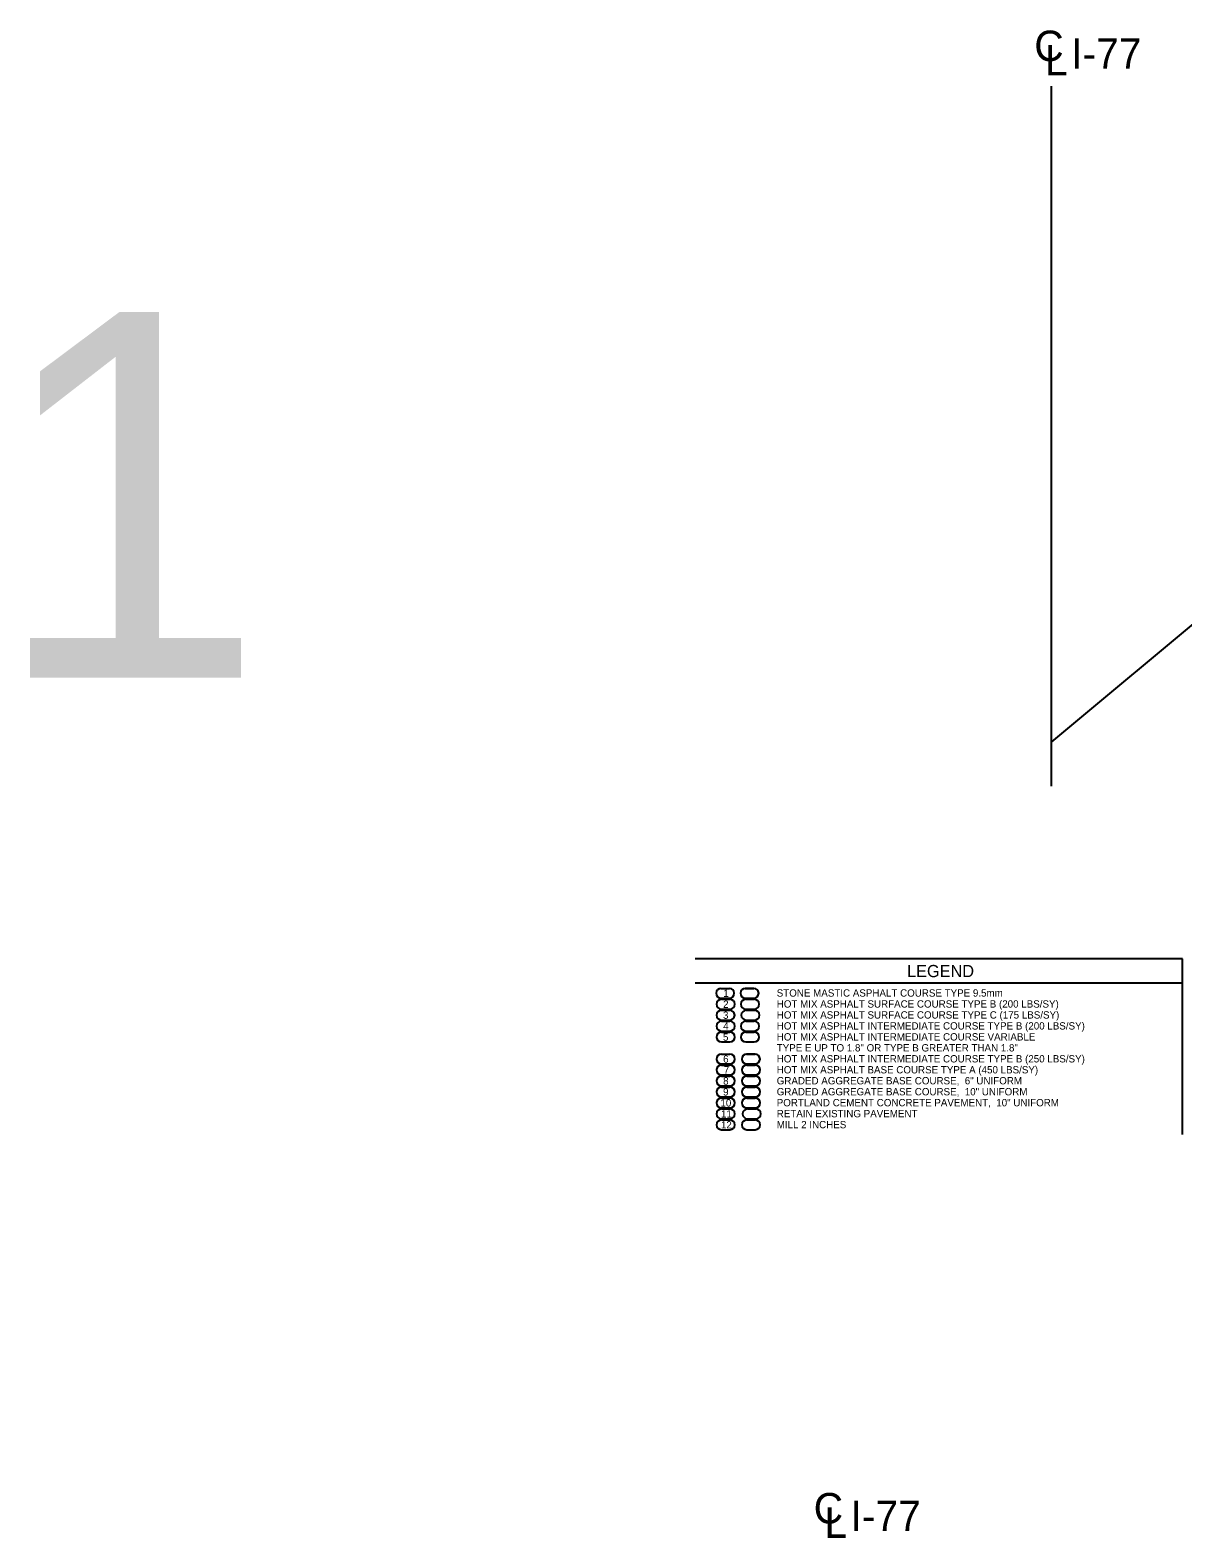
# Model space of a CAD drawing. Extents: x 2003207 to 2014043, y 843846 to 860154.
# Drawn here: x 2013561.2 to 2013655.7, y 844892.9 to 845016.6 of the extents above; entities that cross this region are included whole.
import ezdxf

# ---------------------------------------------------------------- set-up
doc = ezdxf.new("R2010")
doc.units = 0
for name, color, linetype in [('RD_EX_Road', 7, 'Continuous'), ('RD_EX_Road_txCode', 7, 'Continuous'), ('RD_QTY_ConcPave', 7, 'Continuous'), ('RD_QTY_Intermediate', 7, 'Continuous'), ('RD_QTY_Milling', 7, 'Continuous'), ('RD_QTY_PermVeg', 7, 'Continuous'), ('RD_QTY_Surf_Course', 7, 'Continuous'), ('RD_SHT_Bndy', 7, 'Continuous'), ('RD_SHT_TX', 7, 'Continuous'), ('RD_TX_Misc1', 7, 'Continuous'), ('RD_TX_Misc2', 7, 'Continuous'), ('RD_TX_TypSect', 7, 'Continuous')]:
    doc.layers.add(name, color=color, linetype=linetype)

msp = doc.modelspace()

# ---------------------------------------------------------------- linework, layer by layer
at = {"layer": 'RD_EX_Road'}
for p, q in [((2013620.72, 844928.09), (2013620.02, 844928.09)), ((2013620.02, 844927.29), (2013620.72, 844927.29)), ((2013620.66, 844927.19), (2013619.96, 844927.19)), ((2013619.96, 844926.39), (2013620.66, 844926.39))]:
    msp.add_line(p, q, dxfattribs=at)
for centre, start, end in [((2013620.02, 844927.69), 90, 270), ((2013620.72, 844927.69), 270, 90), ((2013619.96, 844926.79), 90, 270), ((2013620.66, 844926.79), 270, 90)]:
    msp.add_arc(centre, 0.4, start, end, dxfattribs=at)
at = {"layer": 'RD_QTY_ConcPave'}
for p, q in [((2013620.66, 844930.79), (2013619.96, 844930.79)), ((2013619.96, 844929.99), (2013620.66, 844929.99)), ((2013620.66, 844929.89), (2013619.96, 844929.89)), ((2013619.96, 844929.09), (2013620.66, 844929.09)), ((2013620.66, 844928.99), (2013619.96, 844928.99)), ((2013619.96, 844928.19), (2013620.66, 844928.19))]:
    msp.add_line(p, q, dxfattribs=at)
for centre, start, end in [((2013619.96, 844930.39), 90, 270), ((2013619.96, 844929.49), 90, 270), ((2013620.66, 844930.39), 270, 90), ((2013620.66, 844929.49), 270, 90), ((2013619.96, 844928.59), 90, 270), ((2013620.66, 844928.59), 270, 90)]:
    msp.add_arc(centre, 0.4, start, end, dxfattribs=at)
at = {"layer": 'RD_QTY_Intermediate'}
for p, q in [((2013620.58, 844935.29), (2013619.88, 844935.29)), ((2013619.88, 844934.49), (2013620.58, 844934.49)), ((2013620.58, 844934.39), (2013619.88, 844934.39)), ((2013619.88, 844933.59), (2013620.58, 844933.59)), ((2013620.65, 844932.59), (2013619.95, 844932.59)), ((2013619.95, 844931.79), (2013620.65, 844931.79)), ((2013620.66, 844931.69), (2013619.96, 844931.69)), ((2013619.96, 844930.89), (2013620.66, 844930.89))]:
    msp.add_line(p, q, dxfattribs=at)
for centre, start, end in [((2013619.88, 844934.89), 90, 270), ((2013620.58, 844934.89), 270, 90), ((2013619.88, 844933.99), 90, 270), ((2013620.58, 844933.99), 270, 90), ((2013619.95, 844932.19), 90, 270), ((2013620.65, 844932.19), 270, 90), ((2013619.96, 844931.29), 90, 270), ((2013620.66, 844931.29), 270, 90)]:
    msp.add_arc(centre, 0.4, start, end, dxfattribs=at)
at = {"layer": 'RD_QTY_Milling'}
for p, q in [((2013620.66, 844927.19), (2013619.96, 844927.19)), ((2013619.96, 844926.39), (2013620.66, 844926.39))]:
    msp.add_line(p, q, dxfattribs=at)
for centre, start, end in [((2013619.96, 844926.79), 90, 270), ((2013620.66, 844926.79), 270, 90)]:
    msp.add_arc(centre, 0.4, start, end, dxfattribs=at)
at = {"layer": 'RD_QTY_PermVeg'}
msp.add_line((2013676.96, 844984.89), (2013644.96, 844958.23), dxfattribs=at)
at = {"layer": 'RD_QTY_Surf_Course'}
for p, q in [((2013620.54, 844937.99), (2013619.84, 844937.99)), ((2013619.84, 844937.19), (2013620.54, 844937.19)), ((2013620.58, 844937.09), (2013619.88, 844937.09)), ((2013619.88, 844936.29), (2013620.58, 844936.29)), ((2013620.61, 844936.19), (2013619.91, 844936.19)), ((2013619.91, 844935.39), (2013620.61, 844935.39))]:
    msp.add_line(p, q, dxfattribs=at)
for centre, start, end in [((2013619.84, 844937.59), 90, 270), ((2013620.54, 844937.59), 270, 90), ((2013619.88, 844936.69), 90, 270), ((2013619.91, 844935.79), 90, 270), ((2013620.58, 844936.69), 270, 90), ((2013620.61, 844935.79), 270, 90)]:
    msp.add_arc(centre, 0.4, start, end, dxfattribs=at)
at = {"layer": 'RD_SHT_Bndy'}
for p, q in [((2013655.72, 844940.41), (2013615.72, 844940.41)), ((2013655.72, 844938.41), (2013655.72, 844940.41)), ((2013655.72, 844938.41), (2013615.72, 844938.41)), ((2013655.72, 844925.99), (2013655.72, 844938.41))]:
    msp.add_line(p, q, dxfattribs=at)
at = {"layer": 'RD_TX_Misc2'}
for p, q in [((2013617.84, 844937.99), (2013618.54, 844937.99)), ((2013617.84, 844937.19), (2013618.54, 844937.19)), ((2013619.84, 844937.99), (2013620.54, 844937.99)), ((2013619.84, 844937.19), (2013620.54, 844937.19)), ((2013617.87, 844936.19), (2013618.57, 844936.19)), ((2013617.88, 844937.09), (2013618.58, 844937.09)), ((2013617.88, 844936.29), (2013618.58, 844936.29)), ((2013619.88, 844937.09), (2013620.58, 844937.09)), ((2013619.88, 844936.29), (2013620.58, 844936.29)), ((2013619.91, 844936.19), (2013620.61, 844936.19)), ((2013617.87, 844935.39), (2013618.57, 844935.39)), ((2013617.88, 844935.29), (2013618.58, 844935.29)), ((2013619.88, 844935.29), (2013620.58, 844935.29)), ((2013619.91, 844935.39), (2013620.61, 844935.39)), ((2013617.88, 844934.49), (2013618.58, 844934.49)), ((2013617.88, 844934.39), (2013618.58, 844934.39)), ((2013617.88, 844933.59), (2013618.58, 844933.59)), ((2013619.88, 844934.49), (2013620.58, 844934.49)), ((2013619.88, 844934.39), (2013620.58, 844934.39)), ((2013619.88, 844933.59), (2013620.58, 844933.59)), ((2013617.88, 844932.59), (2013618.58, 844932.59)), ((2013619.95, 844932.59), (2013620.65, 844932.59)), ((2013617.88, 844931.79), (2013618.58, 844931.79)), ((2013617.88, 844931.69), (2013618.58, 844931.69)), ((2013619.95, 844931.79), (2013620.65, 844931.79)), ((2013619.96, 844931.69), (2013620.66, 844931.69)), ((2013617.88, 844930.89), (2013618.58, 844930.89)), ((2013617.88, 844930.79), (2013618.58, 844930.79)), ((2013617.88, 844929.99), (2013618.58, 844929.99)), ((2013617.88, 844929.89), (2013618.58, 844929.89)), ((2013619.96, 844930.89), (2013620.66, 844930.89)), ((2013619.96, 844930.79), (2013620.66, 844930.79)), ((2013619.96, 844929.99), (2013620.66, 844929.99)), ((2013619.96, 844929.89), (2013620.66, 844929.89)), ((2013617.88, 844929.09), (2013618.58, 844929.09)), ((2013617.88, 844928.99), (2013618.58, 844928.99)), ((2013619.96, 844929.09), (2013620.66, 844929.09)), ((2013619.96, 844928.99), (2013620.66, 844928.99)), ((2013617.88, 844928.19), (2013618.58, 844928.19)), ((2013617.88, 844928.09), (2013618.58, 844928.09)), ((2013617.88, 844927.29), (2013618.58, 844927.29)), ((2013619.96, 844928.19), (2013620.66, 844928.19)), ((2013620.02, 844928.09), (2013620.72, 844928.09)), ((2013620.02, 844927.29), (2013620.72, 844927.29)), ((2013617.88, 844927.19), (2013618.58, 844927.19)), ((2013617.88, 844926.39), (2013618.58, 844926.39)), ((2013619.96, 844927.19), (2013620.66, 844927.19)), ((2013619.96, 844926.39), (2013620.66, 844926.39))]:
    msp.add_line(p, q, dxfattribs=at)
for centre, start, end in [((2013617.84, 844937.59), 90, 270), ((2013618.54, 844937.59), 270, 90), ((2013619.84, 844937.59), 90, 270), ((2013620.54, 844937.59), 270, 90), ((2013617.87, 844935.79), 90, 270), ((2013617.88, 844936.69), 90, 270), ((2013618.57, 844935.79), 270, 90), ((2013618.58, 844936.69), 270, 90), ((2013619.88, 844936.69), 90, 270), ((2013619.91, 844935.79), 90, 270), ((2013620.58, 844936.69), 270, 90), ((2013620.61, 844935.79), 270, 90), ((2013617.88, 844934.89), 90, 270), ((2013618.58, 844934.89), 270, 90), ((2013619.88, 844934.89), 90, 270), ((2013620.58, 844934.89), 270, 90), ((2013617.88, 844933.99), 90, 270), ((2013618.58, 844933.99), 270, 90), ((2013619.88, 844933.99), 90, 270), ((2013620.58, 844933.99), 270, 90), ((2013617.88, 844932.19), 90, 270), ((2013618.58, 844932.19), 270, 90), ((2013619.95, 844932.19), 90, 270), ((2013620.65, 844932.19), 270, 90), ((2013617.88, 844931.29), 90, 270), ((2013618.58, 844931.29), 270, 90), ((2013619.96, 844931.29), 90, 270), ((2013620.66, 844931.29), 270, 90), ((2013617.88, 844930.39), 90, 270), ((2013617.88, 844929.49), 90, 270), ((2013618.58, 844930.39), 270, 90), ((2013618.58, 844929.49), 270, 90), ((2013619.96, 844930.39), 90, 270), ((2013619.96, 844929.49), 90, 270), ((2013620.66, 844930.39), 270, 90), ((2013620.66, 844929.49), 270, 90), ((2013617.88, 844928.59), 90, 270), ((2013618.58, 844928.59), 270, 90), ((2013619.96, 844928.59), 90, 270), ((2013620.66, 844928.59), 270, 90), ((2013617.88, 844927.69), 90, 270), ((2013618.58, 844927.69), 270, 90), ((2013620.02, 844927.69), 90, 270), ((2013620.72, 844927.69), 270, 90), ((2013617.88, 844926.79), 90, 270), ((2013618.58, 844926.79), 270, 90), ((2013619.96, 844926.79), 90, 270), ((2013620.66, 844926.79), 270, 90)]:
    msp.add_arc(centre, 0.4, start, end, dxfattribs=at)
at = {"layer": 'RD_TX_TypSect'}
msp.add_line((2013644.96, 844954.58), (2013644.96, 845012.03), dxfattribs=at)

# ---------------------------------------------------------------- texts
at = {"layer": 'RD_EX_Road_txCode'}
for s, height, p in [('LEGEND', 1, (2013633.11, 844938.91)), ('STONE MASTIC ASPHALT COURSE TYPE 9.5mm', 0.6, (2013622.42, 844937.31)), ('HOT MIX ASPHALT SURFACE COURSE TYPE B (200 LBS/SY)', 0.6, (2013622.42, 844936.41)), ('HOT MIX ASPHALT SURFACE COURSE TYPE C (175 LBS/SY)', 0.6, (2013622.42, 844935.51)), ('HOT MIX ASPHALT INTERMEDIATE COURSE TYPE B (200 LBS/SY)', 0.6, (2013622.42, 844934.61)), ('TYPE E UP TO 1.8" OR TYPE B GREATER THAN 1.8"', 0.6, (2013622.42, 844932.81)), ('HOT MIX ASPHALT INTERMEDIATE COURSE VARIABLE ', 0.6, (2013622.42, 844933.71)), ('HOT MIX ASPHALT INTERMEDIATE COURSE TYPE B (250 LBS/SY)', 0.6, (2013622.42, 844931.91)), ('HOT MIX ASPHALT BASE COURSE TYPE A (450 LBS/SY)', 0.6, (2013622.42, 844931.01)), ('GRADED AGGREGATE BASE COURSE,  6" UNIFORM', 0.6, (2013622.42, 844930.11)), ('GRADED AGGREGATE BASE COURSE,  10" UNIFORM', 0.6, (2013622.42, 844929.21)), ('PORTLAND CEMENT CONCRETE PAVEMENT,  10" UNIFORM', 0.6, (2013622.42, 844928.31)), ('RETAIN EXISTING PAVEMENT', 0.6, (2013622.42, 844927.41)), ('MILL 2 INCHES', 0.6, (2013622.42, 844926.51))]:
    msp.add_text(s, height=height, dxfattribs=at).set_placement(p)
at = {"layer": 'RD_SHT_TX'}
msp.add_text('1', height=30, dxfattribs=at).set_placement((2013558.11, 844963.49))
at = {"layer": 'RD_TX_Misc1'}
for s, p in [('C', (2013643.55, 845014.08)), ('L', (2013644.43, 845012.9)), ('I-77', (2013646.58, 845013.45)), ('C', (2013625.45, 844894.08)), ('L', (2013626.33, 844892.9)), ('I-77', (2013628.48, 844893.45))]:
    msp.add_text(s, height=2.5, dxfattribs=at).set_placement(p)
at = {"layer": 'RD_TX_Misc2'}
for s, p in [('1', (2013618.04, 844937.29)), ('3', (2013618.01, 844935.49)), ('2', (2013618.02, 844936.39)), ('4', (2013618.02, 844934.59)), ('5', (2013618.01, 844933.69)), ('6', (2013618.02, 844931.89)), ('7 ', (2013618.07, 844930.99)), ('8', (2013618.02, 844930.09)), ('9', (2013618.02, 844929.19)), ('10', (2013617.8, 844928.29)), ('11', (2013617.85, 844927.39)), ('12', (2013617.84, 844926.49))]:
    msp.add_text(s, height=0.6, dxfattribs=at).set_placement(p)

doc.saveas('drawing.dxf')
